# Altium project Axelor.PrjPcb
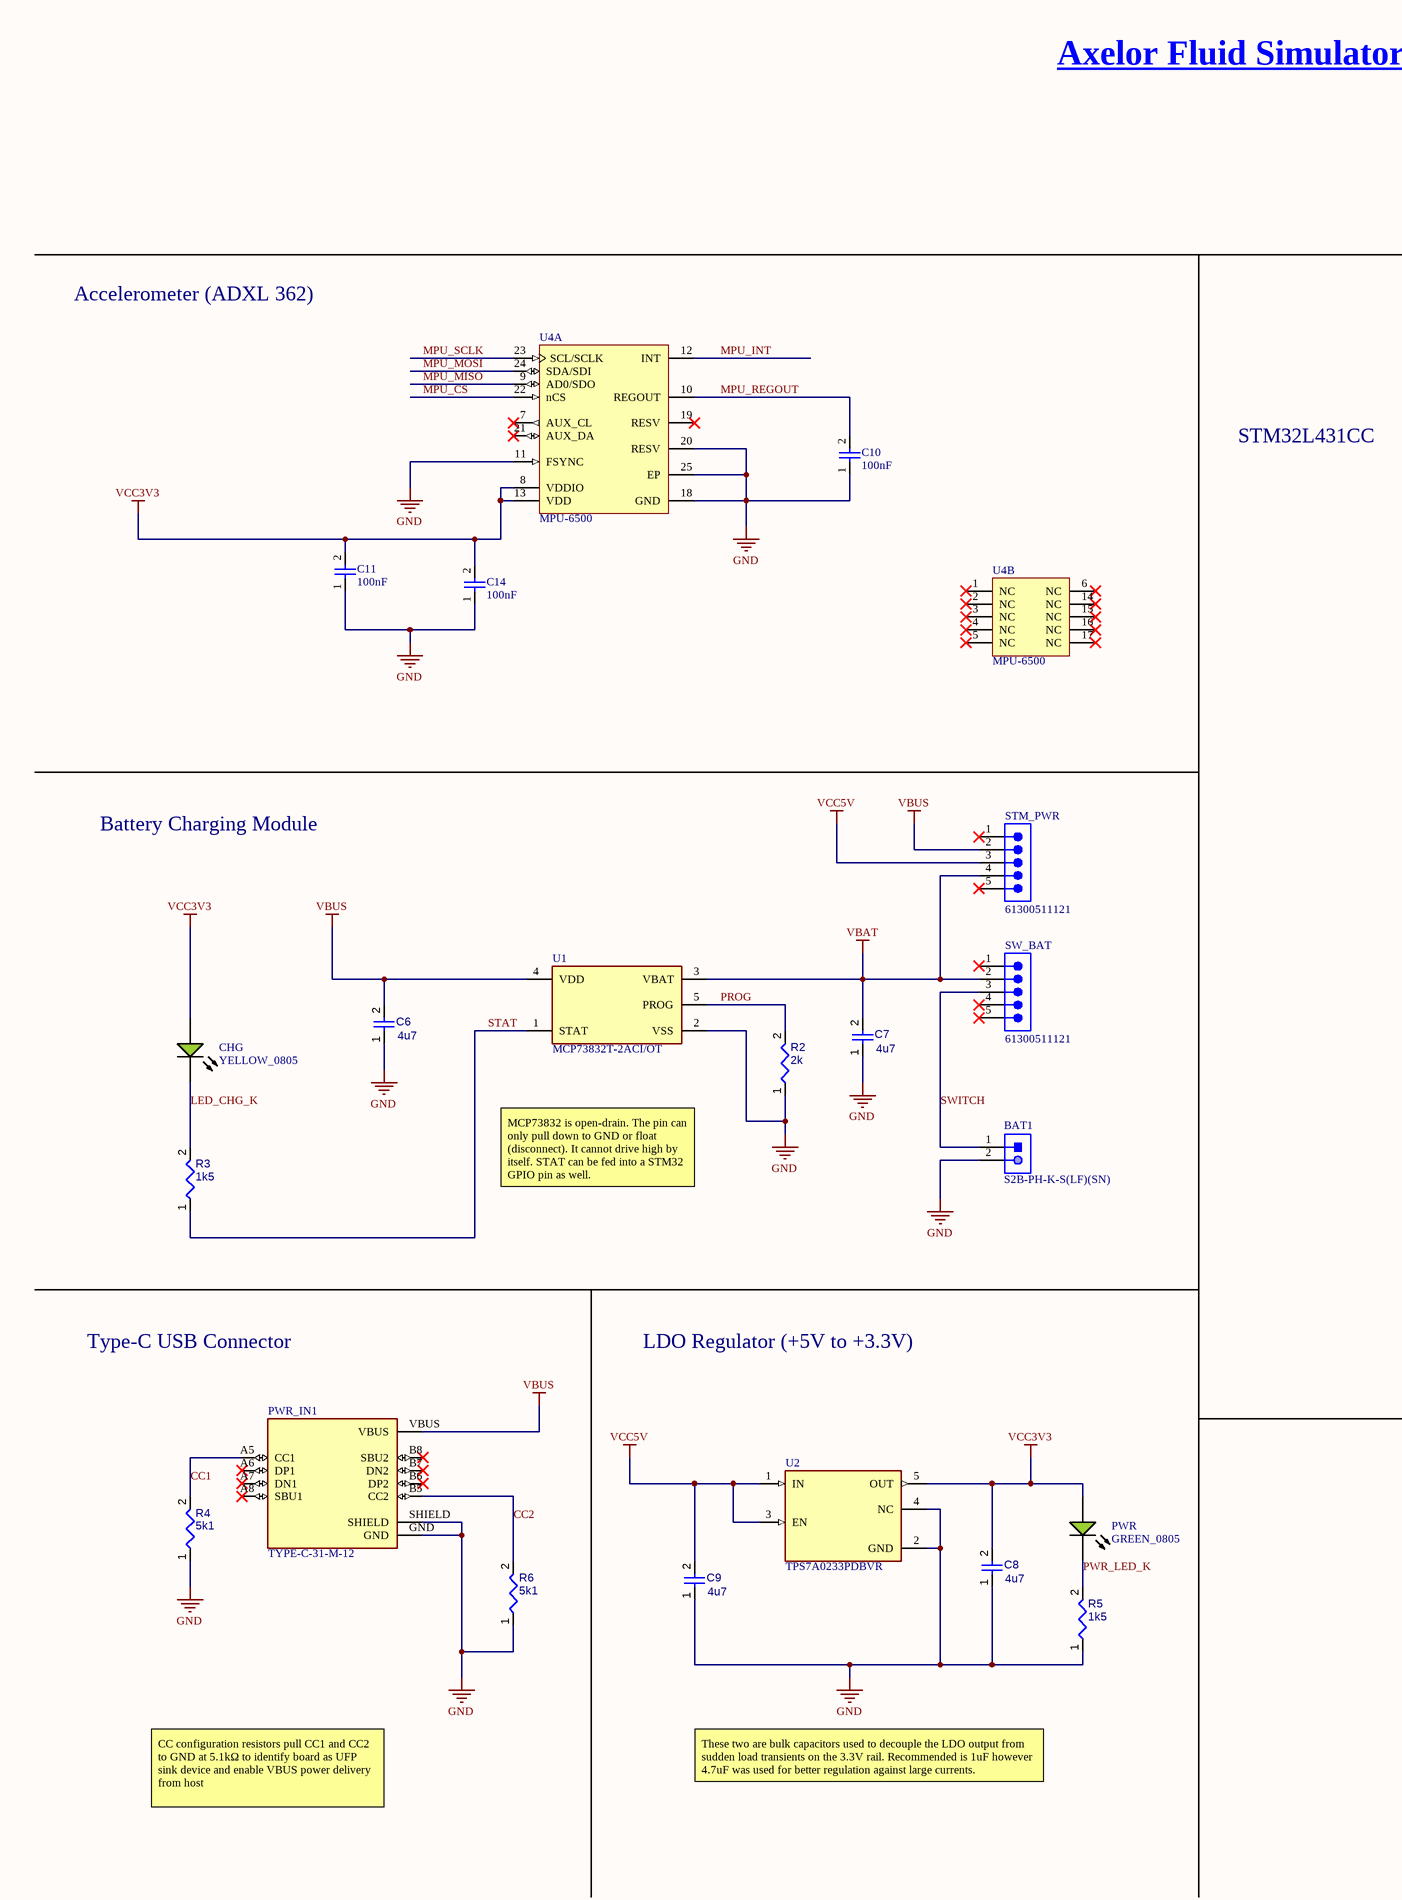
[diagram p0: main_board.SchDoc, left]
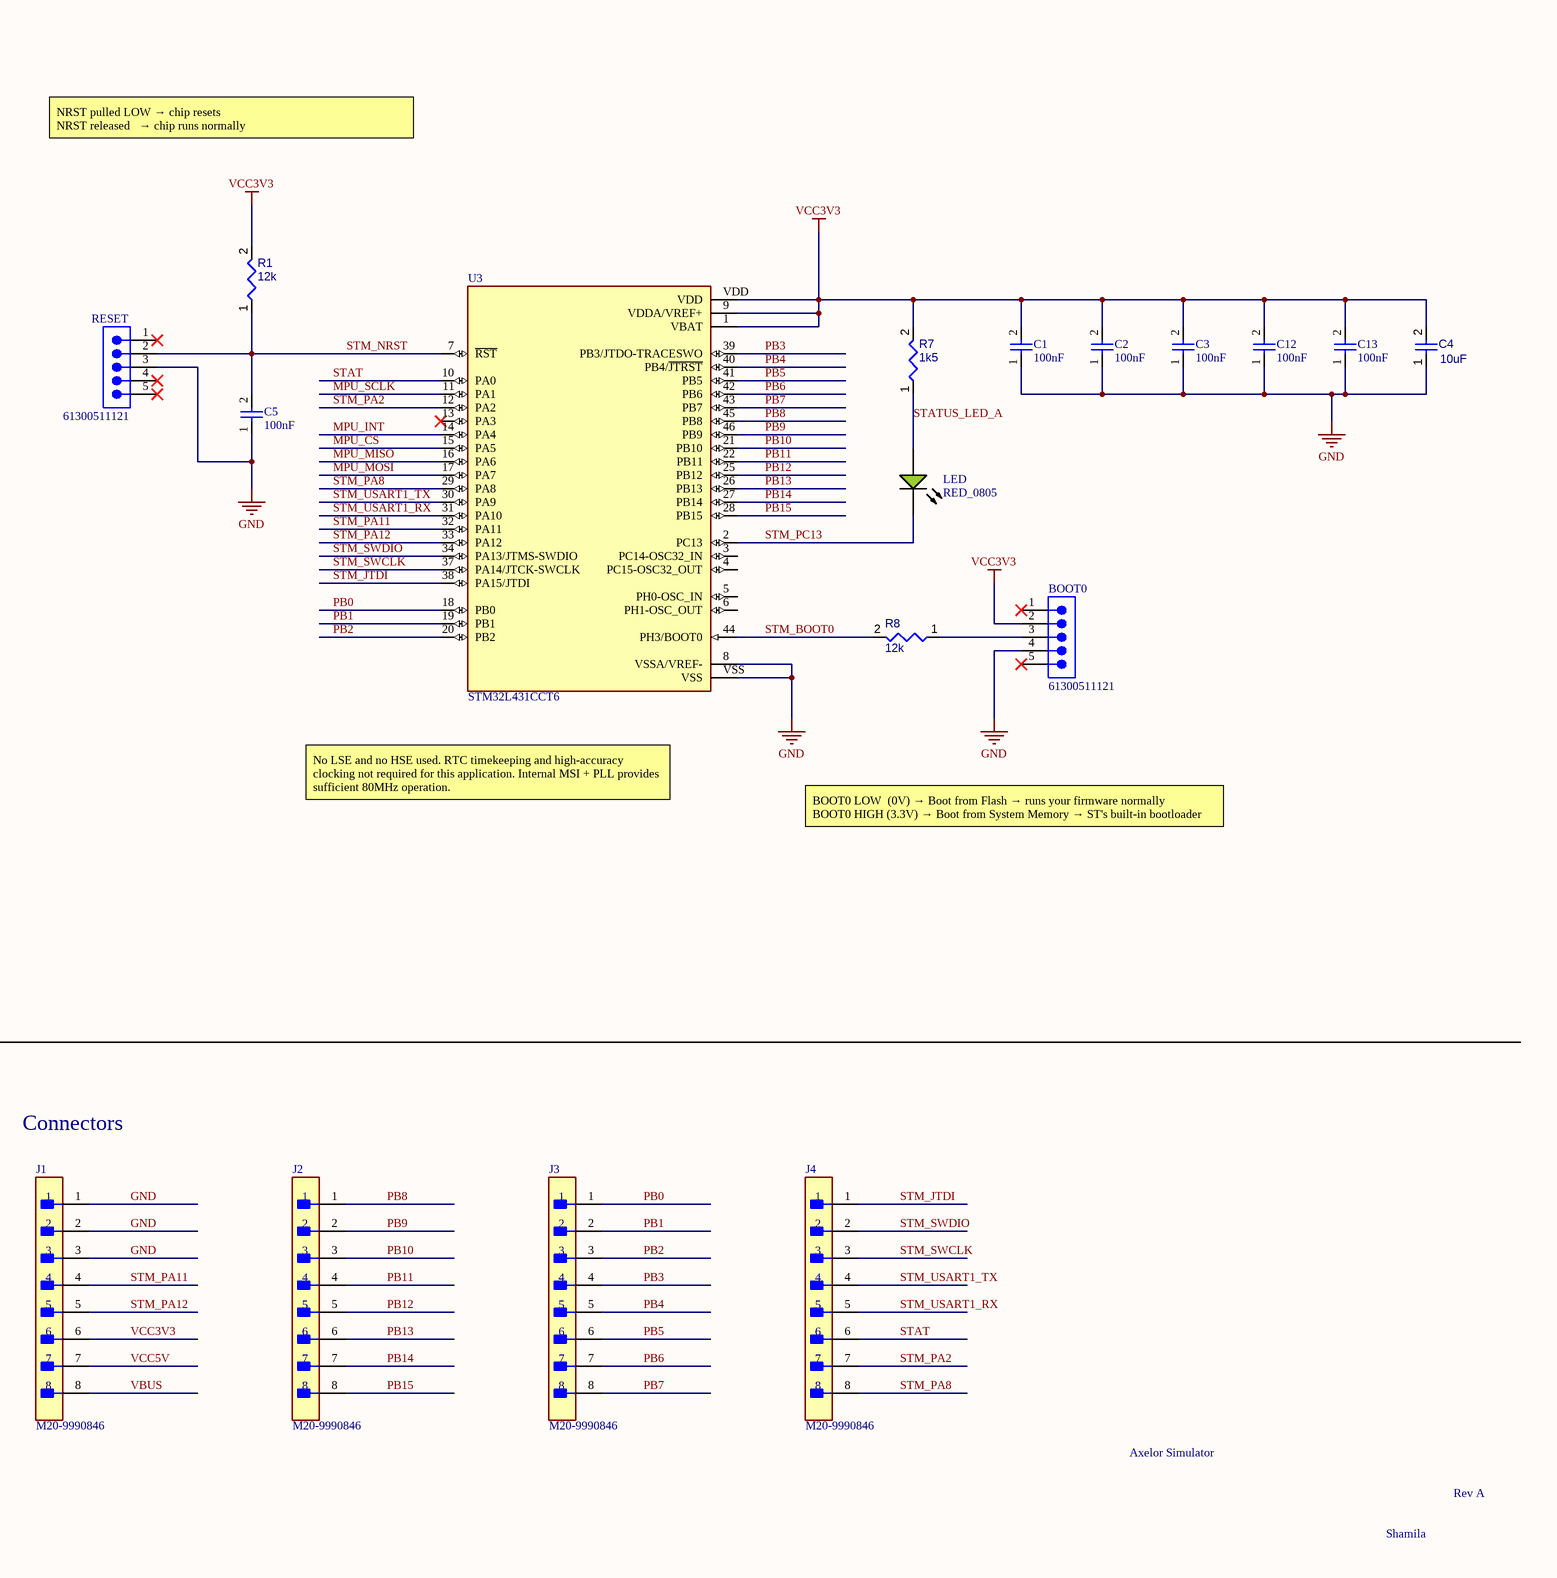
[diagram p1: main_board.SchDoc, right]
2 sheets, 281 parts. Net scope: global (net labels, ports and power ports of the same name join across sheets).
Board file: axelor_pcb.PcbDoc
Sheets:
  main_board.SchDoc
  led_matrix.SchDoc

## Sheet main_board.SchDoc
size A2; SheetNumber: 1; SheetTotal: 2

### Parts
BAT1  S2B-PH-K-S(LF)(SN)  [JST-S2B-PH-K-S_V]
BOOT0  61300511121  [61300511121]
C1  100nF  [CAPC1050X55X23ML05T13]
C2  100nF  [CAPC1050X55X23ML05T13]
C3  100nF  [CAPC1050X55X23ML05T13]
C4  10uF  [CAPC0603(1608)100_L]
C5  100nF  [CAPC1050X55X23ML05T13]
C6  4u7  [CAPC0603(1608)100_L]
C7  4u7  [CAPC0603(1608)100_L]
C8  4u7  [CAPC0603(1608)100_L]
C9  4u7  [CAPC0603(1608)100_L]
C10  100nF  [CAPC1050X55X23ML05T13]
C11  100nF  [CAPC1050X55X23ML05T13]
C12  100nF  [CAPC1050X55X23ML05T13]
C13  100nF  [CAPC1050X55X23ML05T13]
C14  100nF  [CAPC1050X55X23ML05T13]
CHG  YELLOW_0805  [EVRL-17-21SYGC_V]
J1  M20-9990846  [FP-M20-9990846-MFG]
J2  M20-9990846  [FP-M20-9990846-MFG]
J3  M20-9990846  [FP-M20-9990846-MFG]
J4  M20-9990846  [FP-M20-9990846-MFG]
LED  RED_0805  [EVRL-17-21SYGC_V]
PWR  GREEN_0805  [EVRL-17-21SYGC_V]
PWR_IN1  TYPE-C-31-M-12  [HRO_TYPE-C-31-M-12]
R1  12k  [RESC0402(1005)_L]
R2  2k  [RESC0402(1005)_L]
R3  1k5  [RESC0402(1005)_L]
R4  5k1  [RESC0402(1005)_L]
R5  1k5  [RESC0402(1005)_L]
R6  5k1  [RESC0402(1005)_L]
R7  1k5  [RESC0402(1005)_L]
R8  12k  [RESC0402(1005)_L]
RESET  61300511121  [61300511121]
STM_PWR  61300511121  [61300511121]
SW_BAT  61300511121  [61300511121]
U1  MCP73832T-2ACI/OT  [FP-C04-091-OT-MFG]
U2  TPS7A0233PDBVR  [FP-DBV0005A-IPC_B]
U3  STM32L431CCT6  [QFP50P900X900X160-48N]
U4  MPU-6500  [INSE-MPU-6500-QFN24_M]  (parts A,B of 2)

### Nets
GND: BAT1.2 BOOT0.4 C1.1 C2.1 C3.1 C4.1 C5.1 C6.1 C7.1 C8.1 C9.1 C10.1 C11.1 C12.1 C13.1 C14.1 J1.1 J1.2 J1.3 PWR_IN1.GND PWR_IN1.SHIELD R2.1 R4.1 R5.1 R6.1 RESET.3 U1.2(VSS) U2.2(GND) U2.4(NC) U3.8(VSSA/VREF-) U3.VSS U4.11(FSYNC) U4.18(GND) U4.20(RESV) U4.25(EP)
VBAT: C7.2 STM_PWR.4 SW_BAT.2 U1.3(VBAT)
VBUS: C6.2 J1.8 PWR_IN1.VBUS STM_PWR.2 U1.4(VDD)
VCC3V3: BOOT0.2 C1.2 C2.2 C3.2 C4.2 C8.2 C11.2 C12.2 C13.2 C14.2 CHG.1(A) J1.6 PWR.1(A) R1.2 R7.2 U2.5(OUT) U3.1(VBAT) U3.9(VDDA/VREF+) U3.VDD U4.8(VDDIO) U4.13(VDD)
VCC5V: C9.2 J1.7 STM_PWR.3 U2.1(IN) U2.3(EN)
CC1: PWR_IN1.A5(CC1) R4.2
CC2: PWR_IN1.B5(CC2) R6.2
LED_CHG_K: CHG.2(K) R3.2
MPU_CS: U3.15(PA5) U4.22(nCS)
MPU_INT: U3.14(PA4) U4.12(INT)
MPU_MISO: U3.16(PA6) U4.9(AD0/SDO)
MPU_MOSI: U3.17(PA7) U4.24(SDA/SDI)
MPU_REGOUT: C10.2 U4.10(REGOUT)
MPU_SCLK: U3.11(PA1) U4.23(SCL/SCLK)
PB0: J3.1 U3.18(PB0)
PB1: J3.2 U3.19(PB1)
PB2: J3.3 U3.20(PB2)
PB3: J3.4 U3.39(PB3/JTDO-TRACESWO)
PB4: J3.5 U3.40(PB4/~{JTRST})
PB5: J3.6 U3.41(PB5)
PB6: J3.7 U3.42(PB6)
PB7: J3.8 U3.43(PB7)
PB8: J2.1 U3.45(PB8)
PB9: J2.2 U3.46(PB9)
PB10: J2.3 U3.21(PB10)
PB11: J2.4 U3.22(PB11)
PB12: J2.5 U3.25(PB12)
PB13: J2.6 U3.26(PB13)
PB14: J2.7 U3.27(PB14)
PB15: J2.8 U3.28(PB15)
PROG: R2.2 U1.5(PROG)
PWR_LED_K: PWR.2(K) R5.2
STAT: J4.6 R3.1 U1.1(STAT) U3.10(PA0)
STATUS_LED_A: LED.1(A) R7.1
STM_BOOT0: R8.2 U3.44(PH3/BOOT0)
STM_JTDI: J4.1 U3.38(PA15/JTDI)
STM_NRST: C5.2 R1.1 RESET.2 U3.7(~{RST})
STM_PA2: J4.7 U3.12(PA2)
STM_PA8: J4.8 U3.29(PA8)
STM_PA11: J1.4 U3.32(PA11)
STM_PA12: J1.5 U3.33(PA12)
STM_PC13: LED.2(K) U3.2(PC13)
STM_SWCLK: J4.3 U3.37(PA14/JTCK-SWCLK)
STM_SWDIO: J4.2 U3.34(PA13/JTMS-SWDIO)
STM_USART1_RX: J4.5 U3.31(PA10)
STM_USART1_TX: J4.4 U3.30(PA9)
SWITCH: BAT1.1 SW_BAT.3
NetBOOT0_3: BOOT0.3 R8.1

Not connected (* = marked no-connect by the designer): BOOT0 1* 5*; PWR_IN1 A6(DP1)* A7(DN1)* A8(SBU1)* B6(DP2)* B7(DN2)* B8(SBU2)*; RESET 1* 4* 5*; STM_PWR 1* 5*; SW_BAT 1* 4* 5*; U3 3(PC14-OSC32_IN) 4(PC15-OSC32_OUT) 5(PH0-OSC_IN) 6(PH1-OSC_OUT) 13(PA3)*; U4 1(NC)* 2(NC)* 3(NC)* 4(NC)* 5(NC)* 6(NC)* 7(AUX_CL)* 14(NC)* 15(NC)* 16(NC)* 17(NC)* 19(RESV)* 21(AUX_DA)*

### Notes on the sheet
- Axelor Fluid Simulator
- Accelerometer (ADXL 362)
- STM32L431CC
- NRST pulled LOW → chip resets
  NRST released   → chip runs normally
- Battery Charging Module
- MCP73832 is open-drain. The pin can only pull down to GND or float (disconnect). It cannot drive high by itself. STAT can be fed into a STM32 GPIO pin as well.
- No LSE and no HSE used. RTC timekeeping and high-accuracy clocking not required for this application. Internal MSI + PLL provides sufficient 80MHz operation.
- BOOT0 LOW  (0V) → Boot from Flash → runs your firmware normally
  BOOT0 HIGH (3.3V) → Boot from System Memory → ST's built-in bootloader
- Type-C USB Connector
- LDO Regulator (+5V to +3.3V)
- Connectors
- Type @ to refer to a designator
- CC configuration resistors pull CC1 and CC2 to GND at 5.1kΩ to identify board as UFP sink device and enable VBUS power delivery from host
- These two are bulk capacitors used to decouple the LDO output from sudden load transients on the 3.3V rail. Recommended is 1uF however 4.7uF was used for better regulation against large currents.
- Axelor Simulator
- Shamila
- Rev A

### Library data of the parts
BAT1 = CMP-1755-00004-1: Male Header, Pitch 2 mm, 1 x 2 Position, Height 4.8 mm, Tail Length 3.4 mm, -25 to 85 degC, RoHS, Bulk; Case\Package: Radial; Tolerance: 20%; Capacitance: 10 uF; Voltage Rating (DC): 50 V
BOOT0 RESET STM_PWR SW_BAT = CMP-1502-01068-4: THT Vertical Pin Header WR-PHD, Pitch 2.54 mm, Single Row, 5 pins; Number of Contacts: 5; Connector Type: Male Pin; Operating Supply Voltage: 250V; Contact Resistance: 20mΩ; Gender: Male; Pitch: 2.54mm; Current Rating: 3A
C1-C3 C5 C10-C14 = CMP-2000-05439-1: Chip Capacitor, 100 nF, +/- 10%, 16 V, -55 to 125 degC, 0402 (1005 Metric), RoHS, Tape and Reel; Manufacturer: Samsung Electro-Mechanics; Capacitance: 100000pF; Dielectric: X7R; Rated Voltage: 16V
C4 C6-C9 = CMP-001-00076-4: Chip Capacitor, 4.7µF +/-20%, 10V, 0603, Thickness 1 mm; Tolerance: 10%
CHG = CMP-2000-05496-1: LED Yellow , 60 mW, 25 mA, -40 to 85 degC, 2-Pin SMD, RoHS, Tape and Reel  0805; Manufacturer: Everlight Electronics; Intensity: 31mcd; Forward (Drive) Current: 25mA; Viewing Angle: 140°; Forward Voltage: 2V; Lens Type: Clear
J1-J4 = CMP-15831-000033-1: CONN HEADER VERT 8POS 2.54MM; Connector Type: Male Pin; Gender: Male; Insulation Resistance: 1GR; Number of Positions: 8; Contact Resistance: 30mR; Current Rating: 3A
LED = CMP-2000-05496-1: LED Red , 60 mW, 25 mA, -40 to 85 degC, 2-Pin SMD, RoHS, Tape and Reel  0805; Manufacturer: Everlight Electronics; Intensity: 31mcd; Forward (Drive) Current: 25mA; Viewing Angle: 140°; Forward Voltage: 2V; Lens Type: Clear
PWR = CMP-2000-05496-1: LED Green, 60 mW, 25 mA, -40 to 85 degC, 2-Pin SMD, RoHS, Tape and Reel  0805; Manufacturer: Everlight Electronics; Intensity: 31mcd; Forward (Drive) Current: 25mA; Viewing Angle: 140°; Forward Voltage: 2V; Lens Type: Clear
PWR_IN1 = TYPE-C-31-M-12: USB Connectors 24 Receptacle 1 8.94*7.3mm RoHS; MF: HRO Electronics Co., Ltd.
R1-R8 = CMP-009-00147-3: Chip Resistor, 6,2 kOhms, +/-5 %, 63 mW, -55 to 155 degC, 0402; Tolerance: 5%; Power: 63mW; Value: 6.2k
U1 = CMP-0133-00138-2: IC LI-ION/LI-POLY CTRLR SOT23-5; Output Current: 10mA; Output Voltage: 4.2V; Max Output Current: 500mA; Max Power Dissipation: 1.54W; Min Output Voltage: 4.168V; Number of Channels: 1; Max Supply Voltage: 6V; Min Supply Voltage: 3.75V; Max Output Voltage: 4.5V
U2 = CMP-04917-000286-1: IC REG LINEAR 3.3V 200MA SOT23-5
U3 = STM32L431CCT6: ARMÂ® CortexÂ®-M4 STM32L4 Microcontroller IC 32-Bit Single-Core 80MHz 256KB (256K x 8) FLASH 48-LQFP (7x7); MF: STMicroelectronics
U4 = CMP-2000-05154-1: 3-Axis Gyroscope and 3-Axis Accelerometer Motion Processing Unit with I2C and SPI, 1.71 to 3.45 V, -40 to 85 degC, 24-Pin QFN, RoHS, Tape and Reel; Manufacturer: InvenSense; Online Catalog: MPU-6500Series; Output Type: Digital; Sensor Type: GyroscopeandAccelerometer; Featured Product: InvenSense-MPU-6500Six-Axis(Gyro+Acceleromete)MEMSMotionTrackingDevices; Other Names: 1428-1011-6; Article Library: MCUsasSensorHubs

## Sheet led_matrix.SchDoc
size A1; SheetNumber: 2; SheetTotal: 2
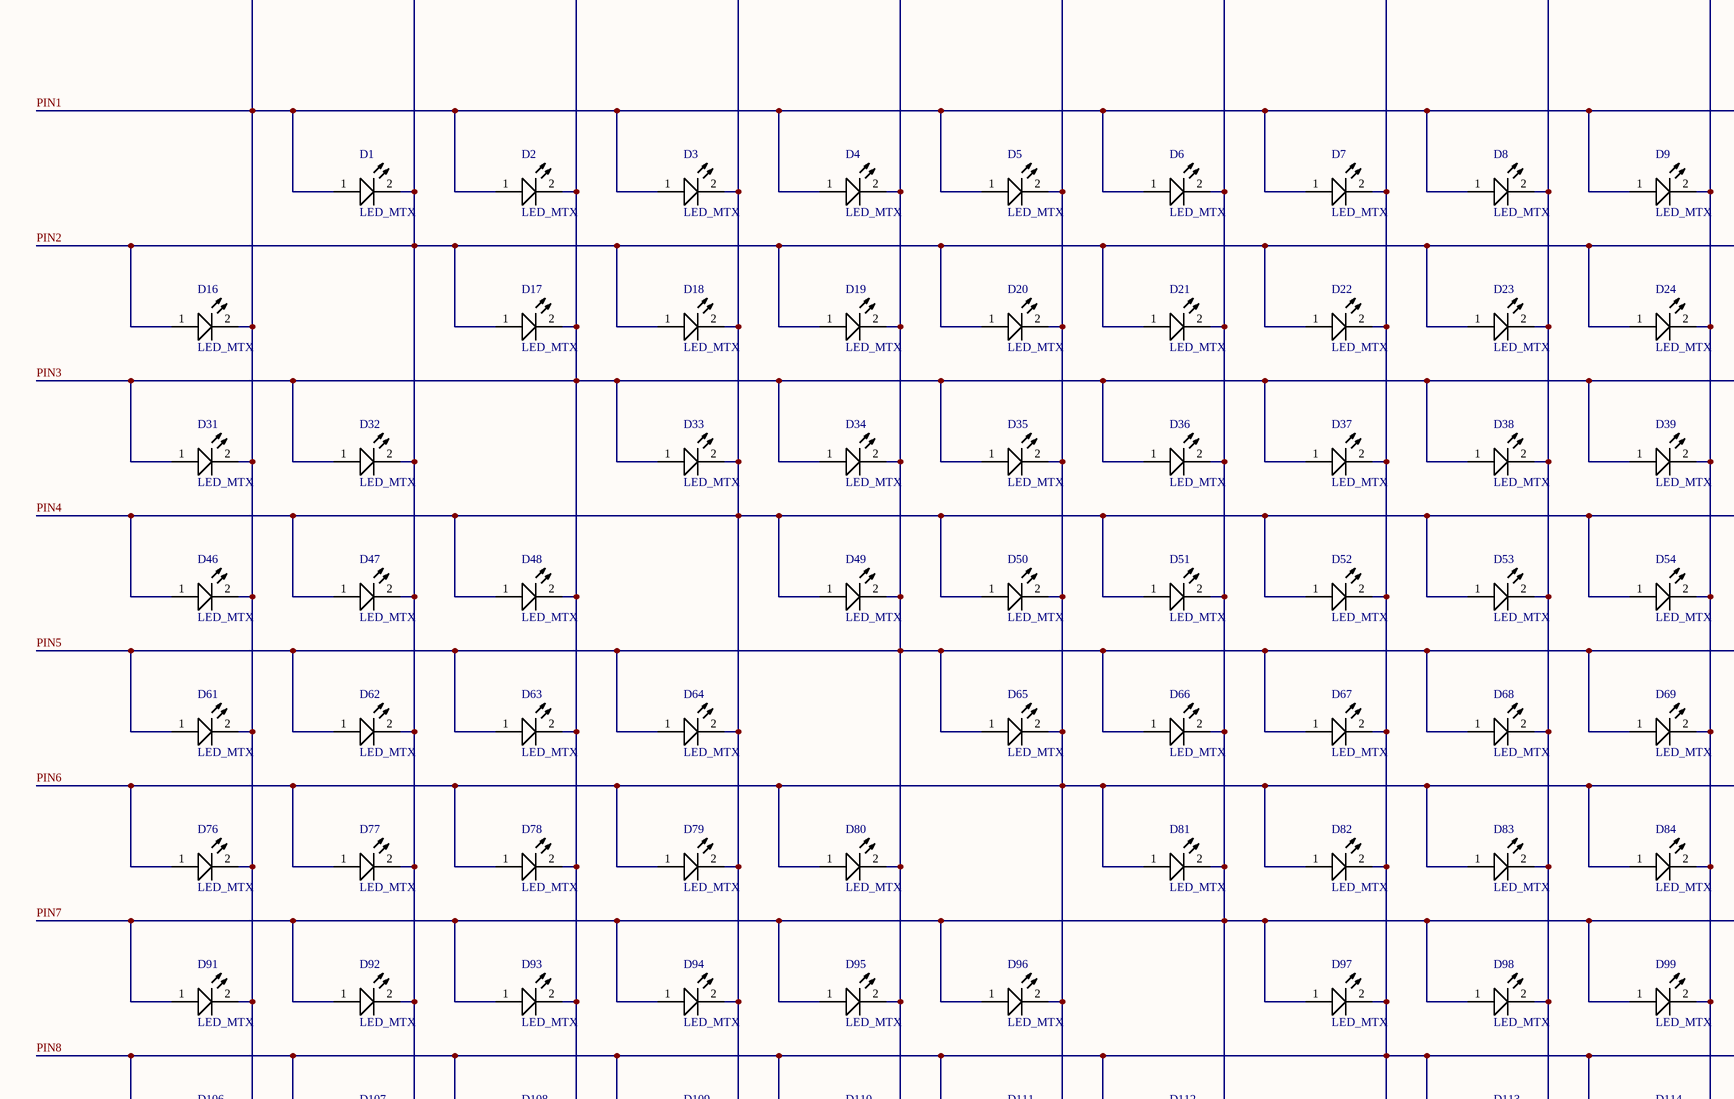
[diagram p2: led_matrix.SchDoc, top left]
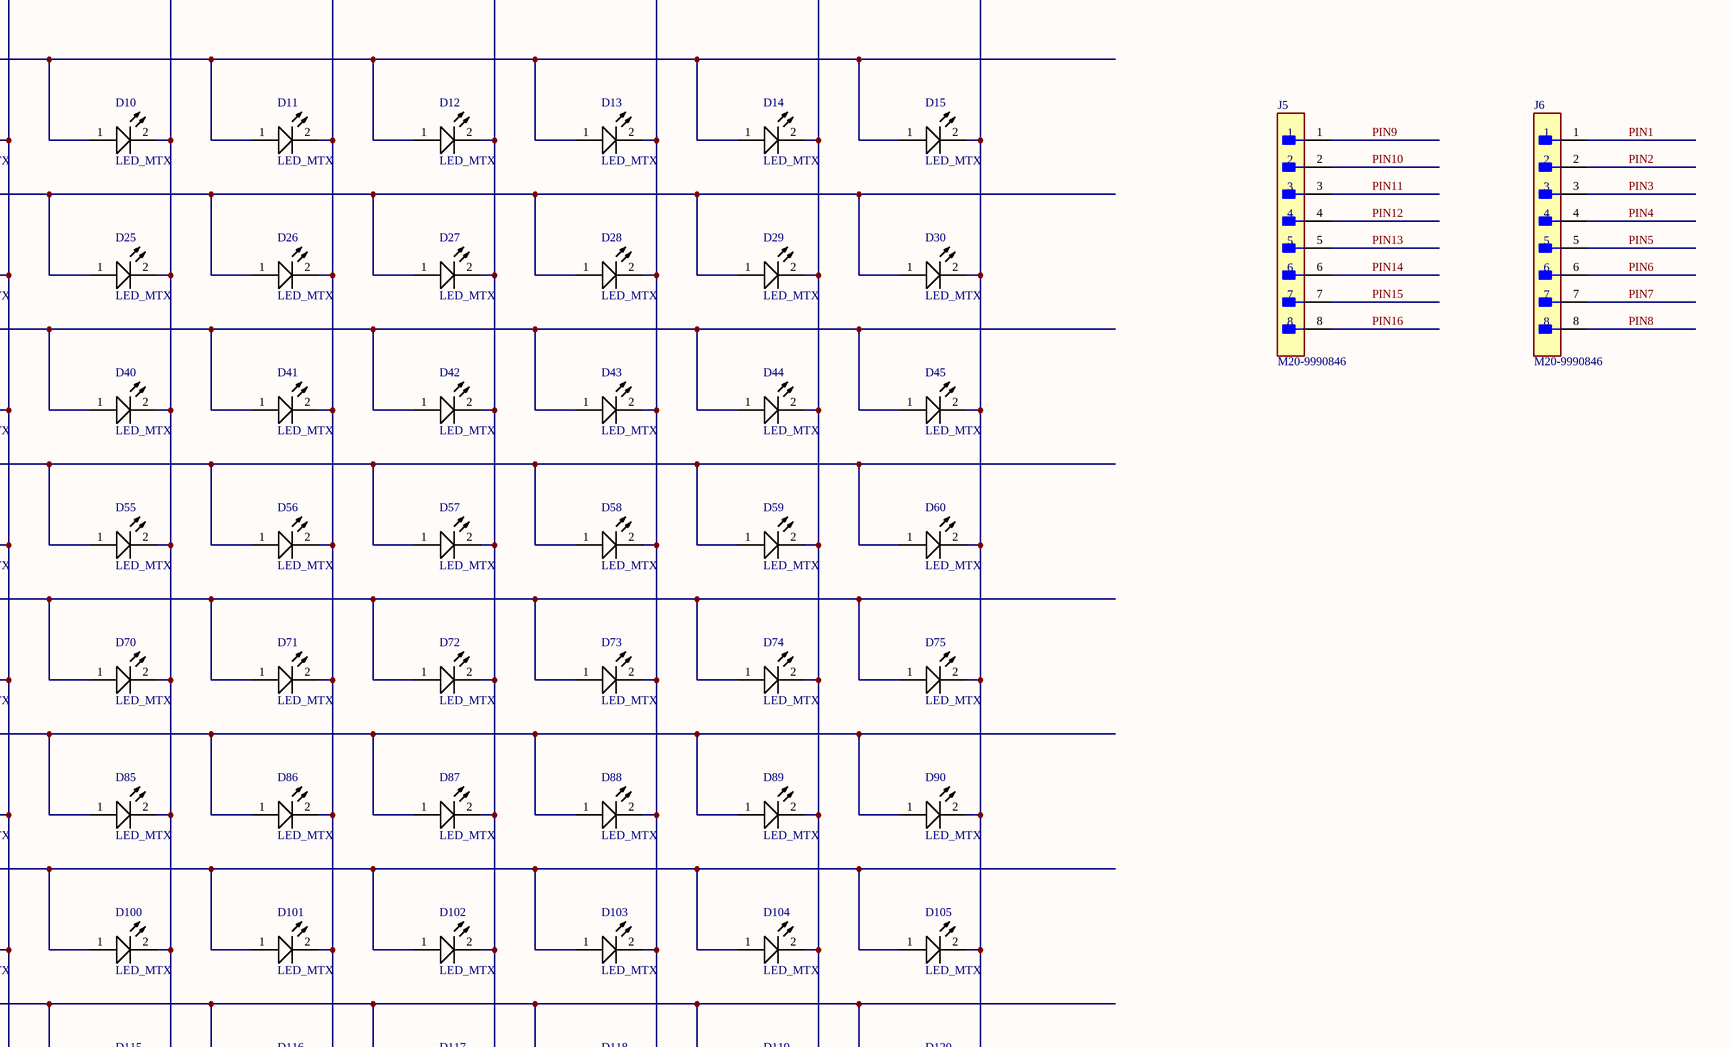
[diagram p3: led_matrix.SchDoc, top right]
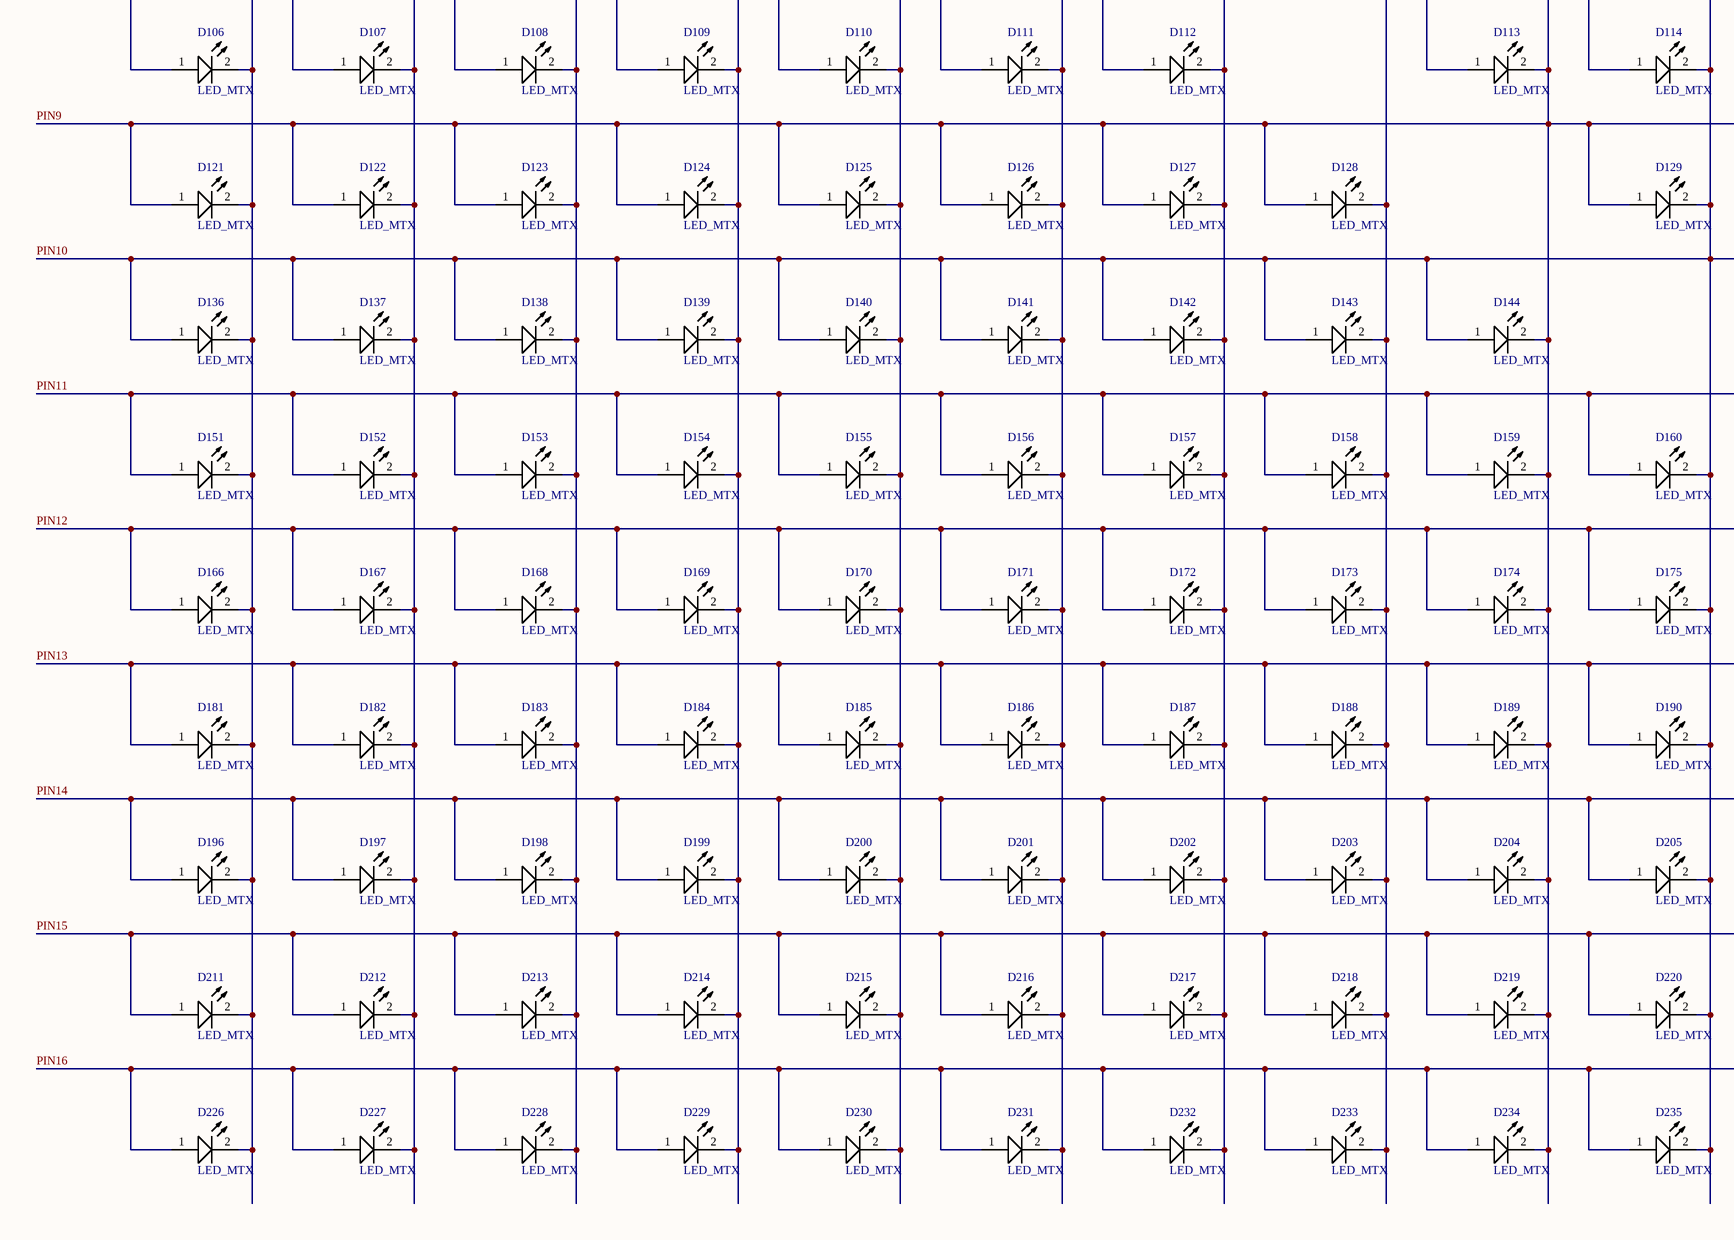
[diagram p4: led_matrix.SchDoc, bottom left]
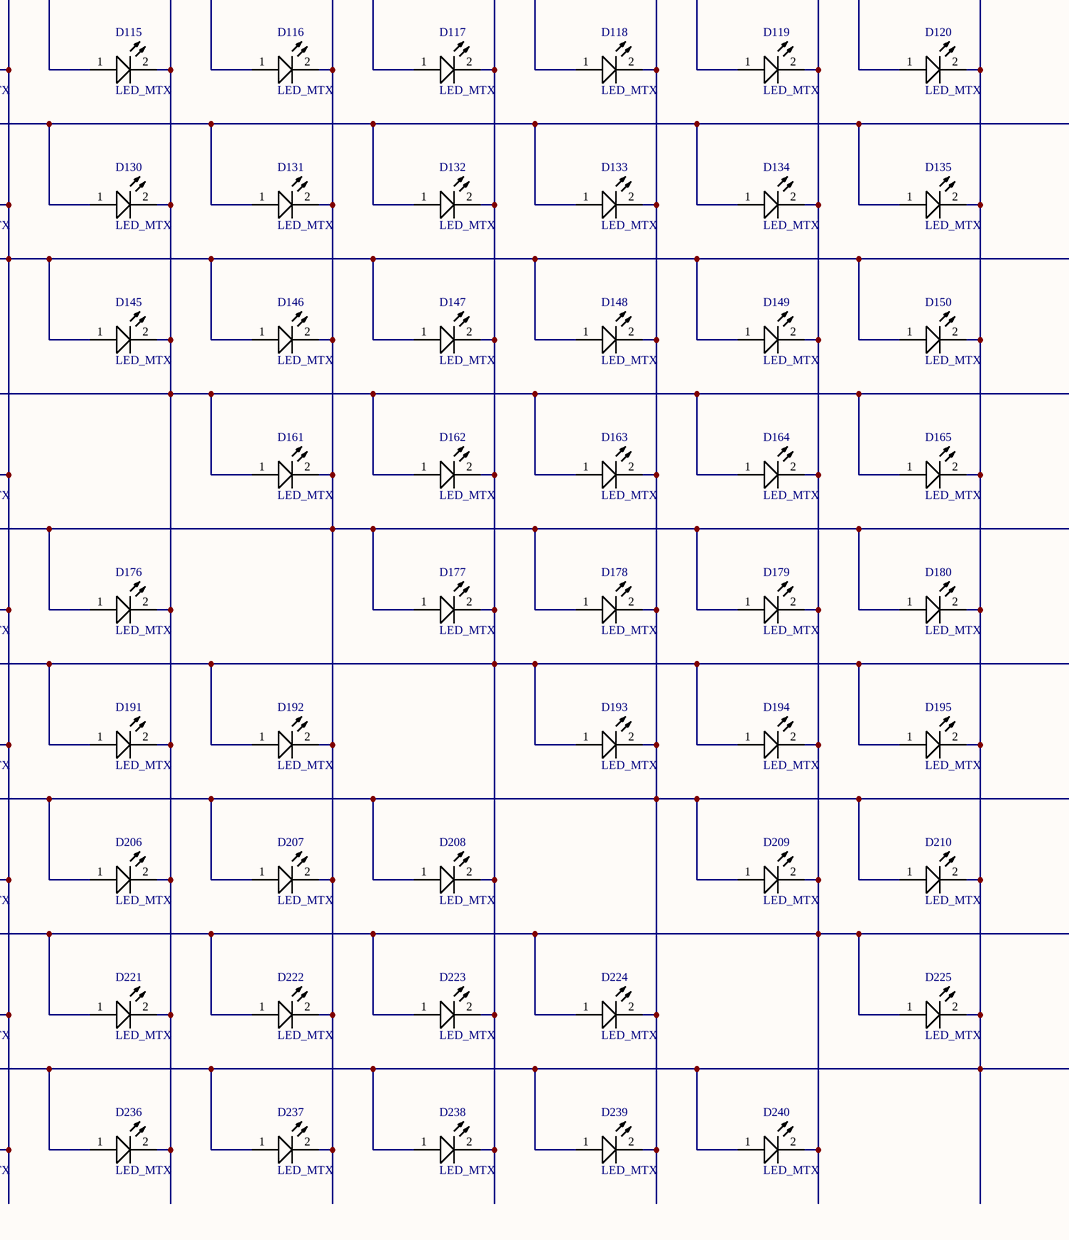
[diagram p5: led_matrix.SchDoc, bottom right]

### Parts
D1  LED_MTX  [EVRL-0402-2_V]
D2  LED_MTX  [EVRL-0402-2_V]
D3  LED_MTX  [EVRL-0402-2_V]
D4  LED_MTX  [EVRL-0402-2_V]
D5  LED_MTX  [EVRL-0402-2_V]
D6  LED_MTX  [EVRL-0402-2_V]
D7  LED_MTX  [EVRL-0402-2_V]
D8  LED_MTX  [EVRL-0402-2_V]
D9  LED_MTX  [EVRL-0402-2_V]
D10  LED_MTX  [EVRL-0402-2_V]
D11  LED_MTX  [EVRL-0402-2_V]
D12  LED_MTX  [EVRL-0402-2_V]
D13  LED_MTX  [EVRL-0402-2_V]
D14  LED_MTX  [EVRL-0402-2_V]
D15  LED_MTX  [EVRL-0402-2_V]
D16  LED_MTX  [EVRL-0402-2_V]
D17  LED_MTX  [EVRL-0402-2_V]
D18  LED_MTX  [EVRL-0402-2_V]
D19  LED_MTX  [EVRL-0402-2_V]
D20  LED_MTX  [EVRL-0402-2_V]
D21  LED_MTX  [EVRL-0402-2_V]
D22  LED_MTX  [EVRL-0402-2_V]
D23  LED_MTX  [EVRL-0402-2_V]
D24  LED_MTX  [EVRL-0402-2_V]
D25  LED_MTX  [EVRL-0402-2_V]
D26  LED_MTX  [EVRL-0402-2_V]
D27  LED_MTX  [EVRL-0402-2_V]
D28  LED_MTX  [EVRL-0402-2_V]
D29  LED_MTX  [EVRL-0402-2_V]
D30  LED_MTX  [EVRL-0402-2_V]
D31  LED_MTX  [EVRL-0402-2_V]
D32  LED_MTX  [EVRL-0402-2_V]
D33  LED_MTX  [EVRL-0402-2_V]
D34  LED_MTX  [EVRL-0402-2_V]
D35  LED_MTX  [EVRL-0402-2_V]
D36  LED_MTX  [EVRL-0402-2_V]
D37  LED_MTX  [EVRL-0402-2_V]
D38  LED_MTX  [EVRL-0402-2_V]
D39  LED_MTX  [EVRL-0402-2_V]
D40  LED_MTX  [EVRL-0402-2_V]
D41  LED_MTX  [EVRL-0402-2_V]
D42  LED_MTX  [EVRL-0402-2_V]
D43  LED_MTX  [EVRL-0402-2_V]
D44  LED_MTX  [EVRL-0402-2_V]
D45  LED_MTX  [EVRL-0402-2_V]
D46  LED_MTX  [EVRL-0402-2_V]
D47  LED_MTX  [EVRL-0402-2_V]
D48  LED_MTX  [EVRL-0402-2_V]
D49  LED_MTX  [EVRL-0402-2_V]
D50  LED_MTX  [EVRL-0402-2_V]
D51  LED_MTX  [EVRL-0402-2_V]
D52  LED_MTX  [EVRL-0402-2_V]
D53  LED_MTX  [EVRL-0402-2_V]
D54  LED_MTX  [EVRL-0402-2_V]
D55  LED_MTX  [EVRL-0402-2_V]
D56  LED_MTX  [EVRL-0402-2_V]
D57  LED_MTX  [EVRL-0402-2_V]
D58  LED_MTX  [EVRL-0402-2_V]
D59  LED_MTX  [EVRL-0402-2_V]
D60  LED_MTX  [EVRL-0402-2_V]
D61  LED_MTX  [EVRL-0402-2_V]
D62  LED_MTX  [EVRL-0402-2_V]
D63  LED_MTX  [EVRL-0402-2_V]
D64  LED_MTX  [EVRL-0402-2_V]
D65  LED_MTX  [EVRL-0402-2_V]
D66  LED_MTX  [EVRL-0402-2_V]
D67  LED_MTX  [EVRL-0402-2_V]
D68  LED_MTX  [EVRL-0402-2_V]
D69  LED_MTX  [EVRL-0402-2_V]
D70  LED_MTX  [EVRL-0402-2_V]
D71  LED_MTX  [EVRL-0402-2_V]
D72  LED_MTX  [EVRL-0402-2_V]
D73  LED_MTX  [EVRL-0402-2_V]
D74  LED_MTX  [EVRL-0402-2_V]
D75  LED_MTX  [EVRL-0402-2_V]
D76  LED_MTX  [EVRL-0402-2_V]
D77  LED_MTX  [EVRL-0402-2_V]
D78  LED_MTX  [EVRL-0402-2_V]
D79  LED_MTX  [EVRL-0402-2_V]
D80  LED_MTX  [EVRL-0402-2_V]
D81  LED_MTX  [EVRL-0402-2_V]
D82  LED_MTX  [EVRL-0402-2_V]
D83  LED_MTX  [EVRL-0402-2_V]
D84  LED_MTX  [EVRL-0402-2_V]
D85  LED_MTX  [EVRL-0402-2_V]
D86  LED_MTX  [EVRL-0402-2_V]
D87  LED_MTX  [EVRL-0402-2_V]
D88  LED_MTX  [EVRL-0402-2_V]
D89  LED_MTX  [EVRL-0402-2_V]
D90  LED_MTX  [EVRL-0402-2_V]
D91  LED_MTX  [EVRL-0402-2_V]
D92  LED_MTX  [EVRL-0402-2_V]
D93  LED_MTX  [EVRL-0402-2_V]
D94  LED_MTX  [EVRL-0402-2_V]
D95  LED_MTX  [EVRL-0402-2_V]
D96  LED_MTX  [EVRL-0402-2_V]
D97  LED_MTX  [EVRL-0402-2_V]
D98  LED_MTX  [EVRL-0402-2_V]
D99  LED_MTX  [EVRL-0402-2_V]
D100  LED_MTX  [EVRL-0402-2_V]
D101  LED_MTX  [EVRL-0402-2_V]
D102  LED_MTX  [EVRL-0402-2_V]
D103  LED_MTX  [EVRL-0402-2_V]
D104  LED_MTX  [EVRL-0402-2_V]
D105  LED_MTX  [EVRL-0402-2_V]
D106  LED_MTX  [EVRL-0402-2_V]
D107  LED_MTX  [EVRL-0402-2_V]
D108  LED_MTX  [EVRL-0402-2_V]
D109  LED_MTX  [EVRL-0402-2_V]
D110  LED_MTX  [EVRL-0402-2_V]
D111  LED_MTX  [EVRL-0402-2_V]
D112  LED_MTX  [EVRL-0402-2_V]
D113  LED_MTX  [EVRL-0402-2_V]
D114  LED_MTX  [EVRL-0402-2_V]
D115  LED_MTX  [EVRL-0402-2_V]
D116  LED_MTX  [EVRL-0402-2_V]
D117  LED_MTX  [EVRL-0402-2_V]
D118  LED_MTX  [EVRL-0402-2_V]
D119  LED_MTX  [EVRL-0402-2_V]
D120  LED_MTX  [EVRL-0402-2_V]
D121  LED_MTX  [EVRL-0402-2_V]
D122  LED_MTX  [EVRL-0402-2_V]
D123  LED_MTX  [EVRL-0402-2_V]
D124  LED_MTX  [EVRL-0402-2_V]
D125  LED_MTX  [EVRL-0402-2_V]
D126  LED_MTX  [EVRL-0402-2_V]
D127  LED_MTX  [EVRL-0402-2_V]
D128  LED_MTX  [EVRL-0402-2_V]
D129  LED_MTX  [EVRL-0402-2_V]
D130  LED_MTX  [EVRL-0402-2_V]
D131  LED_MTX  [EVRL-0402-2_V]
D132  LED_MTX  [EVRL-0402-2_V]
D133  LED_MTX  [EVRL-0402-2_V]
D134  LED_MTX  [EVRL-0402-2_V]
D135  LED_MTX  [EVRL-0402-2_V]
D136  LED_MTX  [EVRL-0402-2_V]
D137  LED_MTX  [EVRL-0402-2_V]
D138  LED_MTX  [EVRL-0402-2_V]
D139  LED_MTX  [EVRL-0402-2_V]
D140  LED_MTX  [EVRL-0402-2_V]
D141  LED_MTX  [EVRL-0402-2_V]
D142  LED_MTX  [EVRL-0402-2_V]
D143  LED_MTX  [EVRL-0402-2_V]
D144  LED_MTX  [EVRL-0402-2_V]
D145  LED_MTX  [EVRL-0402-2_V]
D146  LED_MTX  [EVRL-0402-2_V]
D147  LED_MTX  [EVRL-0402-2_V]
D148  LED_MTX  [EVRL-0402-2_V]
D149  LED_MTX  [EVRL-0402-2_V]
D150  LED_MTX  [EVRL-0402-2_V]
D151  LED_MTX  [EVRL-0402-2_V]
D152  LED_MTX  [EVRL-0402-2_V]
D153  LED_MTX  [EVRL-0402-2_V]
D154  LED_MTX  [EVRL-0402-2_V]
D155  LED_MTX  [EVRL-0402-2_V]
D156  LED_MTX  [EVRL-0402-2_V]
D157  LED_MTX  [EVRL-0402-2_V]
D158  LED_MTX  [EVRL-0402-2_V]
D159  LED_MTX  [EVRL-0402-2_V]
D160  LED_MTX  [EVRL-0402-2_V]
D161  LED_MTX  [EVRL-0402-2_V]
D162  LED_MTX  [EVRL-0402-2_V]
D163  LED_MTX  [EVRL-0402-2_V]
D164  LED_MTX  [EVRL-0402-2_V]
D165  LED_MTX  [EVRL-0402-2_V]
D166  LED_MTX  [EVRL-0402-2_V]
D167  LED_MTX  [EVRL-0402-2_V]
D168  LED_MTX  [EVRL-0402-2_V]
D169  LED_MTX  [EVRL-0402-2_V]
D170  LED_MTX  [EVRL-0402-2_V]
D171  LED_MTX  [EVRL-0402-2_V]
D172  LED_MTX  [EVRL-0402-2_V]
D173  LED_MTX  [EVRL-0402-2_V]
D174  LED_MTX  [EVRL-0402-2_V]
D175  LED_MTX  [EVRL-0402-2_V]
D176  LED_MTX  [EVRL-0402-2_V]
D177  LED_MTX  [EVRL-0402-2_V]
D178  LED_MTX  [EVRL-0402-2_V]
D179  LED_MTX  [EVRL-0402-2_V]
D180  LED_MTX  [EVRL-0402-2_V]
D181  LED_MTX  [EVRL-0402-2_V]
D182  LED_MTX  [EVRL-0402-2_V]
D183  LED_MTX  [EVRL-0402-2_V]
D184  LED_MTX  [EVRL-0402-2_V]
D185  LED_MTX  [EVRL-0402-2_V]
D186  LED_MTX  [EVRL-0402-2_V]
D187  LED_MTX  [EVRL-0402-2_V]
D188  LED_MTX  [EVRL-0402-2_V]
D189  LED_MTX  [EVRL-0402-2_V]
D190  LED_MTX  [EVRL-0402-2_V]
D191  LED_MTX  [EVRL-0402-2_V]
D192  LED_MTX  [EVRL-0402-2_V]
D193  LED_MTX  [EVRL-0402-2_V]
D194  LED_MTX  [EVRL-0402-2_V]
D195  LED_MTX  [EVRL-0402-2_V]
D196  LED_MTX  [EVRL-0402-2_V]
D197  LED_MTX  [EVRL-0402-2_V]
D198  LED_MTX  [EVRL-0402-2_V]
D199  LED_MTX  [EVRL-0402-2_V]
D200  LED_MTX  [EVRL-0402-2_V]
D201  LED_MTX  [EVRL-0402-2_V]
D202  LED_MTX  [EVRL-0402-2_V]
D203  LED_MTX  [EVRL-0402-2_V]
D204  LED_MTX  [EVRL-0402-2_V]
D205  LED_MTX  [EVRL-0402-2_V]
D206  LED_MTX  [EVRL-0402-2_V]
D207  LED_MTX  [EVRL-0402-2_V]
D208  LED_MTX  [EVRL-0402-2_V]
D209  LED_MTX  [EVRL-0402-2_V]
D210  LED_MTX  [EVRL-0402-2_V]
D211  LED_MTX  [EVRL-0402-2_V]
D212  LED_MTX  [EVRL-0402-2_V]
D213  LED_MTX  [EVRL-0402-2_V]
D214  LED_MTX  [EVRL-0402-2_V]
D215  LED_MTX  [EVRL-0402-2_V]
D216  LED_MTX  [EVRL-0402-2_V]
D217  LED_MTX  [EVRL-0402-2_V]
D218  LED_MTX  [EVRL-0402-2_V]
D219  LED_MTX  [EVRL-0402-2_V]
D220  LED_MTX  [EVRL-0402-2_V]
D221  LED_MTX  [EVRL-0402-2_V]
D222  LED_MTX  [EVRL-0402-2_V]
D223  LED_MTX  [EVRL-0402-2_V]
D224  LED_MTX  [EVRL-0402-2_V]
D225  LED_MTX  [EVRL-0402-2_V]
D226  LED_MTX  [EVRL-0402-2_V]
D227  LED_MTX  [EVRL-0402-2_V]
D228  LED_MTX  [EVRL-0402-2_V]
D229  LED_MTX  [EVRL-0402-2_V]
D230  LED_MTX  [EVRL-0402-2_V]
D231  LED_MTX  [EVRL-0402-2_V]
D232  LED_MTX  [EVRL-0402-2_V]
D233  LED_MTX  [EVRL-0402-2_V]
D234  LED_MTX  [EVRL-0402-2_V]
D235  LED_MTX  [EVRL-0402-2_V]
D236  LED_MTX  [EVRL-0402-2_V]
D237  LED_MTX  [EVRL-0402-2_V]
D238  LED_MTX  [EVRL-0402-2_V]
D239  LED_MTX  [EVRL-0402-2_V]
D240  LED_MTX  [EVRL-0402-2_V]
J5  M20-9990846  [FP-M20-9990846-MFG]
J6  M20-9990846  [FP-M20-9990846-MFG]

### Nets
PIN1: D1.1(A) D2.1(A) D3.1(A) D4.1(A) D5.1(A) D6.1(A) D7.1(A) D8.1(A) D9.1(A) D10.1(A) D11.1(A) D12.1(A) D13.1(A) D14.1(A) D15.1(A) D16.2(K) D31.2(K) D46.2(K) D61.2(K) D76.2(K) D91.2(K) D106.2(K) D121.2(K) D136.2(K) D151.2(K) D166.2(K) D181.2(K) D196.2(K) D211.2(K) D226.2(K) J6.1
PIN2: D1.2(K) D16.1(A) D17.1(A) D18.1(A) D19.1(A) D20.1(A) D21.1(A) D22.1(A) D23.1(A) D24.1(A) D25.1(A) D26.1(A) D27.1(A) D28.1(A) D29.1(A) D30.1(A) D32.2(K) D47.2(K) D62.2(K) D77.2(K) D92.2(K) D107.2(K) D122.2(K) D137.2(K) D152.2(K) D167.2(K) D182.2(K) D197.2(K) D212.2(K) D227.2(K) J6.2
PIN3: D2.2(K) D17.2(K) D31.1(A) D32.1(A) D33.1(A) D34.1(A) D35.1(A) D36.1(A) D37.1(A) D38.1(A) D39.1(A) D40.1(A) D41.1(A) D42.1(A) D43.1(A) D44.1(A) D45.1(A) D48.2(K) D63.2(K) D78.2(K) D93.2(K) D108.2(K) D123.2(K) D138.2(K) D153.2(K) D168.2(K) D183.2(K) D198.2(K) D213.2(K) D228.2(K) J6.3
PIN4: D3.2(K) D18.2(K) D33.2(K) D46.1(A) D47.1(A) D48.1(A) D49.1(A) D50.1(A) D51.1(A) D52.1(A) D53.1(A) D54.1(A) D55.1(A) D56.1(A) D57.1(A) D58.1(A) D59.1(A) D60.1(A) D64.2(K) D79.2(K) D94.2(K) D109.2(K) D124.2(K) D139.2(K) D154.2(K) D169.2(K) D184.2(K) D199.2(K) D214.2(K) D229.2(K) J6.4
PIN5: D4.2(K) D19.2(K) D34.2(K) D49.2(K) D61.1(A) D62.1(A) D63.1(A) D64.1(A) D65.1(A) D66.1(A) D67.1(A) D68.1(A) D69.1(A) D70.1(A) D71.1(A) D72.1(A) D73.1(A) D74.1(A) D75.1(A) D80.2(K) D95.2(K) D110.2(K) D125.2(K) D140.2(K) D155.2(K) D170.2(K) D185.2(K) D200.2(K) D215.2(K) D230.2(K) J6.5
PIN6: D5.2(K) D20.2(K) D35.2(K) D50.2(K) D65.2(K) D76.1(A) D77.1(A) D78.1(A) D79.1(A) D80.1(A) D81.1(A) D82.1(A) D83.1(A) D84.1(A) D85.1(A) D86.1(A) D87.1(A) D88.1(A) D89.1(A) D90.1(A) D96.2(K) D111.2(K) D126.2(K) D141.2(K) D156.2(K) D171.2(K) D186.2(K) D201.2(K) D216.2(K) D231.2(K) J6.6
PIN7: D6.2(K) D21.2(K) D36.2(K) D51.2(K) D66.2(K) D81.2(K) D91.1(A) D92.1(A) D93.1(A) D94.1(A) D95.1(A) D96.1(A) D97.1(A) D98.1(A) D99.1(A) D100.1(A) D101.1(A) D102.1(A) D103.1(A) D104.1(A) D105.1(A) D112.2(K) D127.2(K) D142.2(K) D157.2(K) D172.2(K) D187.2(K) D202.2(K) D217.2(K) D232.2(K) J6.7
PIN8: D7.2(K) D22.2(K) D37.2(K) D52.2(K) D67.2(K) D82.2(K) D97.2(K) D106.1(A) D107.1(A) D108.1(A) D109.1(A) D110.1(A) D111.1(A) D112.1(A) D113.1(A) D114.1(A) D115.1(A) D116.1(A) D117.1(A) D118.1(A) D119.1(A) D120.1(A) D128.2(K) D143.2(K) D158.2(K) D173.2(K) D188.2(K) D203.2(K) D218.2(K) D233.2(K) J6.8
PIN9: D8.2(K) D23.2(K) D38.2(K) D53.2(K) D68.2(K) D83.2(K) D98.2(K) D113.2(K) D121.1(A) D122.1(A) D123.1(A) D124.1(A) D125.1(A) D126.1(A) D127.1(A) D128.1(A) D129.1(A) D130.1(A) D131.1(A) D132.1(A) D133.1(A) D134.1(A) D135.1(A) D144.2(K) D159.2(K) D174.2(K) D189.2(K) D204.2(K) D219.2(K) D234.2(K) J5.1
PIN10: D9.2(K) D24.2(K) D39.2(K) D54.2(K) D69.2(K) D84.2(K) D99.2(K) D114.2(K) D129.2(K) D136.1(A) D137.1(A) D138.1(A) D139.1(A) D140.1(A) D141.1(A) D142.1(A) D143.1(A) D144.1(A) D145.1(A) D146.1(A) D147.1(A) D148.1(A) D149.1(A) D150.1(A) D160.2(K) D175.2(K) D190.2(K) D205.2(K) D220.2(K) D235.2(K) J5.2
PIN11: D10.2(K) D25.2(K) D40.2(K) D55.2(K) D70.2(K) D85.2(K) D100.2(K) D115.2(K) D130.2(K) D145.2(K) D151.1(A) D152.1(A) D153.1(A) D154.1(A) D155.1(A) D156.1(A) D157.1(A) D158.1(A) D159.1(A) D160.1(A) D161.1(A) D162.1(A) D163.1(A) D164.1(A) D165.1(A) D176.2(K) D191.2(K) D206.2(K) D221.2(K) D236.2(K) J5.3
PIN12: D11.2(K) D26.2(K) D41.2(K) D56.2(K) D71.2(K) D86.2(K) D101.2(K) D116.2(K) D131.2(K) D146.2(K) D161.2(K) D166.1(A) D167.1(A) D168.1(A) D169.1(A) D170.1(A) D171.1(A) D172.1(A) D173.1(A) D174.1(A) D175.1(A) D176.1(A) D177.1(A) D178.1(A) D179.1(A) D180.1(A) D192.2(K) D207.2(K) D222.2(K) D237.2(K) J5.4
PIN13: D12.2(K) D27.2(K) D42.2(K) D57.2(K) D72.2(K) D87.2(K) D102.2(K) D117.2(K) D132.2(K) D147.2(K) D162.2(K) D177.2(K) D181.1(A) D182.1(A) D183.1(A) D184.1(A) D185.1(A) D186.1(A) D187.1(A) D188.1(A) D189.1(A) D190.1(A) D191.1(A) D192.1(A) D193.1(A) D194.1(A) D195.1(A) D208.2(K) D223.2(K) D238.2(K) J5.5
PIN14: D13.2(K) D28.2(K) D43.2(K) D58.2(K) D73.2(K) D88.2(K) D103.2(K) D118.2(K) D133.2(K) D148.2(K) D163.2(K) D178.2(K) D193.2(K) D196.1(A) D197.1(A) D198.1(A) D199.1(A) D200.1(A) D201.1(A) D202.1(A) D203.1(A) D204.1(A) D205.1(A) D206.1(A) D207.1(A) D208.1(A) D209.1(A) D210.1(A) D224.2(K) D239.2(K) J5.6
PIN15: D14.2(K) D29.2(K) D44.2(K) D59.2(K) D74.2(K) D89.2(K) D104.2(K) D119.2(K) D134.2(K) D149.2(K) D164.2(K) D179.2(K) D194.2(K) D209.2(K) D211.1(A) D212.1(A) D213.1(A) D214.1(A) D215.1(A) D216.1(A) D217.1(A) D218.1(A) D219.1(A) D220.1(A) D221.1(A) D222.1(A) D223.1(A) D224.1(A) D225.1(A) D240.2(K) J5.7
PIN16: D15.2(K) D30.2(K) D45.2(K) D60.2(K) D75.2(K) D90.2(K) D105.2(K) D120.2(K) D135.2(K) D150.2(K) D165.2(K) D180.2(K) D195.2(K) D210.2(K) D225.2(K) D226.1(A) D227.1(A) D228.1(A) D229.1(A) D230.1(A) D231.1(A) D232.1(A) D233.1(A) D234.1(A) D235.1(A) D236.1(A) D237.1(A) D238.1(A) D239.1(A) D240.1(A) J5.8

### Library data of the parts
D1-D240 = CMP-007-00000-2: Chip LED, Blue , 5 V, 10 mA, 30 mW, -40 to 85 degC, 2-Pin SMD (0402), RoHS, Tape and Reel; Manufacturer: Everlight Electronics; Luminous Intensity: 360mcd; Forward Voltage: 2.6V; Viewing Angle: 130degrees; Illumination Colour: White; Power: 30mW; Forward Current: 5mA
J5 J6 = CMP-15831-000033-1: as J1 on sheet main_board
